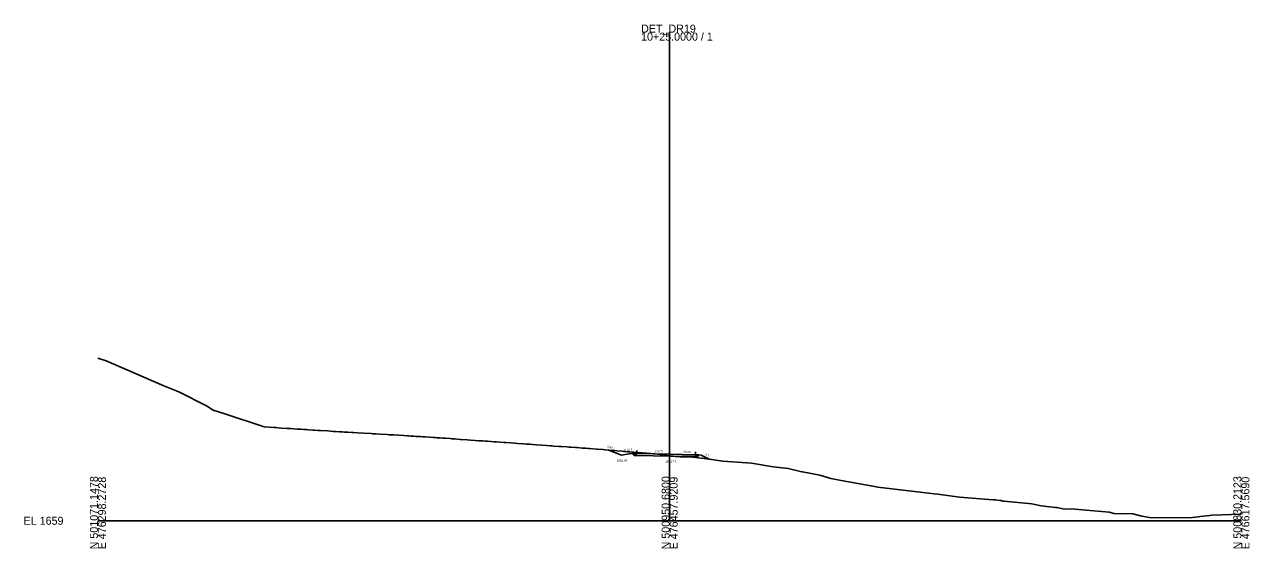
# Model space of a CAD drawing. Extents: x -26 to 403, y -10 to 3059.
# Drawn here: x -25.7 to 402.8, y -9.7 to 173.5 of the extents above; entities that cross this region are included whole.
import ezdxf

# ---------------------------------------------------------------- set-up
doc = ezdxf.new("R2010")
doc.units = 0
for name, color, linetype in [('Exist Cross Section Cell', 7, 'Continuous'), ('Exist XS Center Line Elevation Label', 7, 'Continuous'), ('Exist XS Ground Line', 7, 'Continuous'), ('Prop XS Ditch Slope Text', 7, 'Continuous'), ('Prop XS Ditch Standard Text', 7, 'Continuous'), ('Prop XS Dump Level', 7, 'Continuous'), ('Prop XS Earthwork Shape', 7, 'Continuous'), ('Prop XS EOT Tick Mark', 7, 'Continuous'), ('Prop XS Finish Grade', 7, 'Continuous'), ('Prop XS Finish Grade Earthwork', 7, 'Continuous'), ('Prop XS Finish Grade Pavement', 7, 'Continuous'), ('Prop XS Pvmt Edge Slope', 7, 'Continuous'), ('Prop XS SE Text', 7, 'Continuous'), ('Prop XS Shoulder Borrow Shape', 7, 'Continuous'), ('Prop XS Side Slope Text', 7, 'Continuous'), ('Prop XS Subgrade Earthwork', 7, 'Continuous')]:
    doc.layers.add(name, color=color, linetype=linetype)

msp = doc.modelspace()

# ---------------------------------------------------------------- linework, layer by layer
at = {"layer": 'Exist Cross Section Cell'}
for p, q in [((200, 0), (200, 170.68)), ((0, 0), (200, 0)), ((200, 0), (400, 0))]:
    msp.add_line(p, q, dxfattribs=at)
at = {"layer": 'Exist XS Ground Line'}
msp.add_lwpolyline([(0, 56.89), (2.89, 55.97), (8.22, 53.59), (9.93, 52.88), (23, 47.21), (28.28, 45.06), (37.92, 40.17), (40.32, 38.68), (44.08, 37.54), (58.14, 32.8), (61.61, 32.61), (62.23, 32.57), (63.05, 32.51), (64.25, 32.43), (66.19, 32.3), (67.58, 32.21), (68.47, 32.15), (69.7, 32.08), (71.11, 31.99), (71.95, 31.94), (72.9, 31.88), (73.59, 31.83), (75.14, 31.73), (75.78, 31.69), (76.98, 31.61), (77.84, 31.55), (80.4, 31.39), (82.32, 31.27), (83.13, 31.22), (84.55, 31.14), (85.4, 31.09), (86.24, 31.03), (87.4, 30.97), (88.81, 30.87), (89.36, 30.84), (90.83, 30.76), (93.03, 30.62), (95.61, 30.47), (96.19, 30.43), (97.09, 30.38), (98.79, 30.28), (101.16, 30.14), (101.86, 30.09), (103.45, 29.99), (105.28, 29.88), (107, 29.77), (108.17, 29.7), (108.71, 29.67), (109.5, 29.62), (110.46, 29.56), (111.28, 29.51), (112.87, 29.41), (113.68, 29.36), (114.42, 29.31), (115.96, 29.21), (117.42, 29.12), (118.01, 29.09), (118.6, 29.05), (119.69, 28.98), (120.7, 28.9), (121.01, 28.88), (121.54, 28.84), (123.26, 28.71), (123.81, 28.67), (124.81, 28.6), (126.55, 28.47), (126.92, 28.45), (129.21, 28.28), (130.37, 28.2), (131.93, 28.09), (133.18, 28), (133.72, 27.96), (134.51, 27.91), (135.56, 27.83), (136.29, 27.78), (138.64, 27.61), (139.48, 27.55), (141.94, 27.38), (142.75, 27.32), (144.47, 27.2), (145.67, 27.11), (146.9, 27.02), (148.85, 26.88), (149.76, 26.82), (151.05, 26.73), (151.99, 26.66), (153.36, 26.56), (155.22, 26.43), (156.96, 26.3), (158.21, 26.22), (158.93, 26.17), (159.38, 26.14), (161.37, 26), (162.13, 25.95), (164.17, 25.81), (164.71, 25.77), (165.44, 25.72), (167.02, 25.61), (167.72, 25.56), (169.47, 25.43), (170.65, 25.35), (171.49, 25.29), (171.91, 25.26), (174.39, 25.09), (174.69, 25.07), (176.75, 24.89), (177.41, 24.83), (178.58, 24.73), (180.19, 24.58), (181.55, 24.46), (183.35, 24.3), (183.93, 24.25), (184.3, 24.22), (185.3, 24.14), (186.05, 24.08), (186.74, 24.04), (187.31, 23.99), (188.36, 23.9), (188.9, 23.86), (191.97, 23.65), (194.97, 23.41), (198.45, 22.95), (200, 22.74), (201.4, 22.54), (201.95, 22.47), (203.7, 22.3), (204.54, 22.26), (207.23, 22.3), (213.02, 21.65), (218.55, 20.87), (228.66, 20.1), (236.25, 18.82), (241.48, 18.26), (246.19, 17.15), (246.51, 17.06), (252.52, 15.99), (256.33, 14.75), (261.3, 13.83), (270.46, 12.17), (272.84, 11.8), (292.49, 9.4), (293.78, 9.26), (301.44, 8.27), (313.13, 7.34), (314.03, 7.29), (315.51, 7.06), (315.91, 7.04), (316.59, 6.88), (317.05, 6.81), (326.72, 5.9), (329.95, 5.27), (335.02, 4.68), (335.45, 4.6), (338.11, 4.11), (340.41, 4.12), (345.76, 3.7), (353.78, 3.03), (355.54, 2.52), (361.97, 2.41), (365.16, 1.65), (367.9, 1.19), (372.36, 1.05), (382.9, 1.09), (384.95, 1.36), (385.63, 1.44), (388.92, 1.87), (389.72, 1.98), (400, 2.34)], dxfattribs=at)
at = {"layer": 'Prop XS Dump Level'}
for p, q in [((200, 23.29), (188.5, 23.52)), ((209, 23.11), (200, 23.29))]:
    msp.add_line(p, q, dxfattribs=at)
at = {"layer": 'Prop XS Earthwork Shape'}
for points in [[(200.93, 22.61), (200, 22.63), (188.5, 22.86), (187.63, 22.87), (186.83, 23.47), (185.84, 23.44), (183.17, 22.94), (178.37, 24.75), (178.58, 24.73), (180.19, 24.58), (181.55, 24.46), (183.35, 24.3), (183.93, 24.25), (184.3, 24.22), (185.3, 24.14), (186.05, 24.08), (186.74, 24.04), (187.31, 23.99), (188.36, 23.9), (188.9, 23.86), (191.97, 23.65), (194.97, 23.41), (198.45, 22.95), (200, 22.74)], [(200.93, 22.61), (201.4, 22.54), (201.95, 22.47), (203.7, 22.3), (204.54, 22.26), (207.23, 22.3), (213.02, 21.65), (213.83, 21.54), (211, 22.95), (210.26, 23.01), (209.68, 22.43), (209, 22.45)]]:
    msp.add_lwpolyline(points, close=True, dxfattribs=at)
at = {"layer": 'Prop XS EOT Tick Mark'}
for p, q in [((188.5, 23.52), (188.5, 24.52)), ((209, 23.11), (209, 24.11))]:
    msp.add_line(p, q, dxfattribs=at)
at = {"layer": 'Prop XS Finish Grade'}
for p, q in [((188.5, 23.52), (186.83, 23.47)), ((209, 23.11), (210.26, 23.01))]:
    msp.add_line(p, q, dxfattribs=at)
at = {"layer": 'Prop XS Finish Grade Earthwork'}
for p, q in [((183.17, 22.94), (178.37, 24.75)), ((185.84, 23.44), (183.17, 22.94)), ((186.83, 23.47), (185.84, 23.44)), ((210.26, 23.01), (211, 22.95)), ((211, 22.95), (213.83, 21.54))]:
    msp.add_line(p, q, dxfattribs=at)
at = {"layer": 'Prop XS Finish Grade Pavement'}
for p, q in [((188.5, 23.52), (200, 23.29)), ((200, 23.29), (209, 23.11))]:
    msp.add_line(p, q, dxfattribs=at)
at = {"layer": 'Prop XS Pvmt Edge Slope'}
for p, q in [((188.5, 23.52), (187.63, 22.87)), ((209, 23.11), (209.68, 22.43))]:
    msp.add_line(p, q, dxfattribs=at)
at = {"layer": 'Prop XS Shoulder Borrow Shape'}
for points in [[(188.5, 23.52), (187.63, 22.87), (186.83, 23.47)], [(209.68, 22.43), (210.26, 23.01), (209, 23.11)]]:
    msp.add_lwpolyline(points, close=True, dxfattribs=at)
at = {"layer": 'Prop XS Subgrade Earthwork'}
for p, q in [((187.63, 22.87), (186.83, 23.47)), ((188.5, 22.86), (187.63, 22.87)), ((200, 22.63), (188.5, 22.86)), ((209, 22.45), (200, 22.63)), ((209, 22.45), (209.68, 22.43)), ((209.68, 22.43), (210.26, 23.01))]:
    msp.add_line(p, q, dxfattribs=at)

# ---------------------------------------------------------------- texts
at = {"layer": 'Exist Cross Section Cell'}
for s, p in [('DET_DR19', (190, 170.68)), ('10+25.0000 / 1', (190, 167.88)), ('EL 1659', (-26, -1.4))]:
    msp.add_text(s, height=2.8, dxfattribs=at).set_placement(p)
for s, p in [('N 501071.1478', (0, -10)), ('E 476298.2728', (2.8, -10)), ('N 500950.6800', (200, -10)), ('E 476457.9209', (202.8, -10)), ('N 500830.2123', (400, -10)), ('E 476617.5690', (402.8, -10))]:
    msp.add_text(s, height=2.8, rotation=90, dxfattribs=at).set_placement(p)
at = {"layer": 'Exist XS Center Line Elevation Label'}
msp.add_text('1681.74', height=0.75, dxfattribs=at).set_placement((198.45, 20.36))
at = {"layer": 'Prop XS Ditch Slope Text'}
msp.add_text('5.33:1', height=0.75, rotation=10.624, dxfattribs=at).set_placement((184.23, 24.17))
at = {"layer": 'Prop XS Ditch Standard Text'}
msp.add_text('1681.94', height=0.75, dxfattribs=at).set_placement((181.45, 20.69))
at = {"layer": 'Prop XS Dump Level'}
for p in [(185.84, 23.4), (211, 22.91)]:
    msp.add_text('Case1', height=0.04, dxfattribs=at).set_placement(p)
at = {"layer": 'Prop XS SE Text'}
for p in [(194.85, 23.93), (204.69, 23.73)]:
    msp.add_text('0.020', height=0.75, rotation=358.8542, dxfattribs=at).set_placement(p)
at = {"layer": 'Prop XS Side Slope Text'}
for s, rotation, p in [('2.67:1', 339.4361, (177.99, 25.72)), ('2:1', 333.4349, (212.38, 22.98))]:
    msp.add_text(s, height=0.75, rotation=rotation, dxfattribs=at).set_placement(p)

doc.saveas('drawing.dxf')
